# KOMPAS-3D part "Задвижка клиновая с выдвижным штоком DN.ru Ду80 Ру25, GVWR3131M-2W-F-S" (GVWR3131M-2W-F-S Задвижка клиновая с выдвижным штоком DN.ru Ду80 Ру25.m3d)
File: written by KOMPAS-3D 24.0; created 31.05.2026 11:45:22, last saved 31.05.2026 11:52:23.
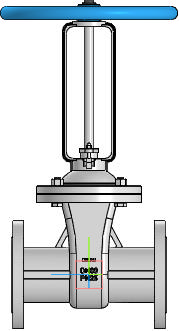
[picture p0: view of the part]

Document properties: Автор: R2D2; Полное имя файла: E:\Работа\Зайцев\GVWR3131M-2W-F-S Задвижка клиновая 30нж64нж DN.ru  Ду50-150 Ру25\исходные данные\DN80\dn80\GVWR3131M-2W-F-S Задвижка клиновая с выдвижным штоком DN.ru Ду80 Ру25.m3d

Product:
- Part/product: Задвижка клиновая с выдвижным штоком DN.ru Ду80 Ру25  | designation GVWR3131M-2W-F-S
    Масса: 25.5
    Раздел спецификации: Прочие изделия
    Примечание: D040-09368

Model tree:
1. Операция без истории:1

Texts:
  GVWR3131M-2W-F-S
